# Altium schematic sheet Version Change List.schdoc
size 645 x 190 mm
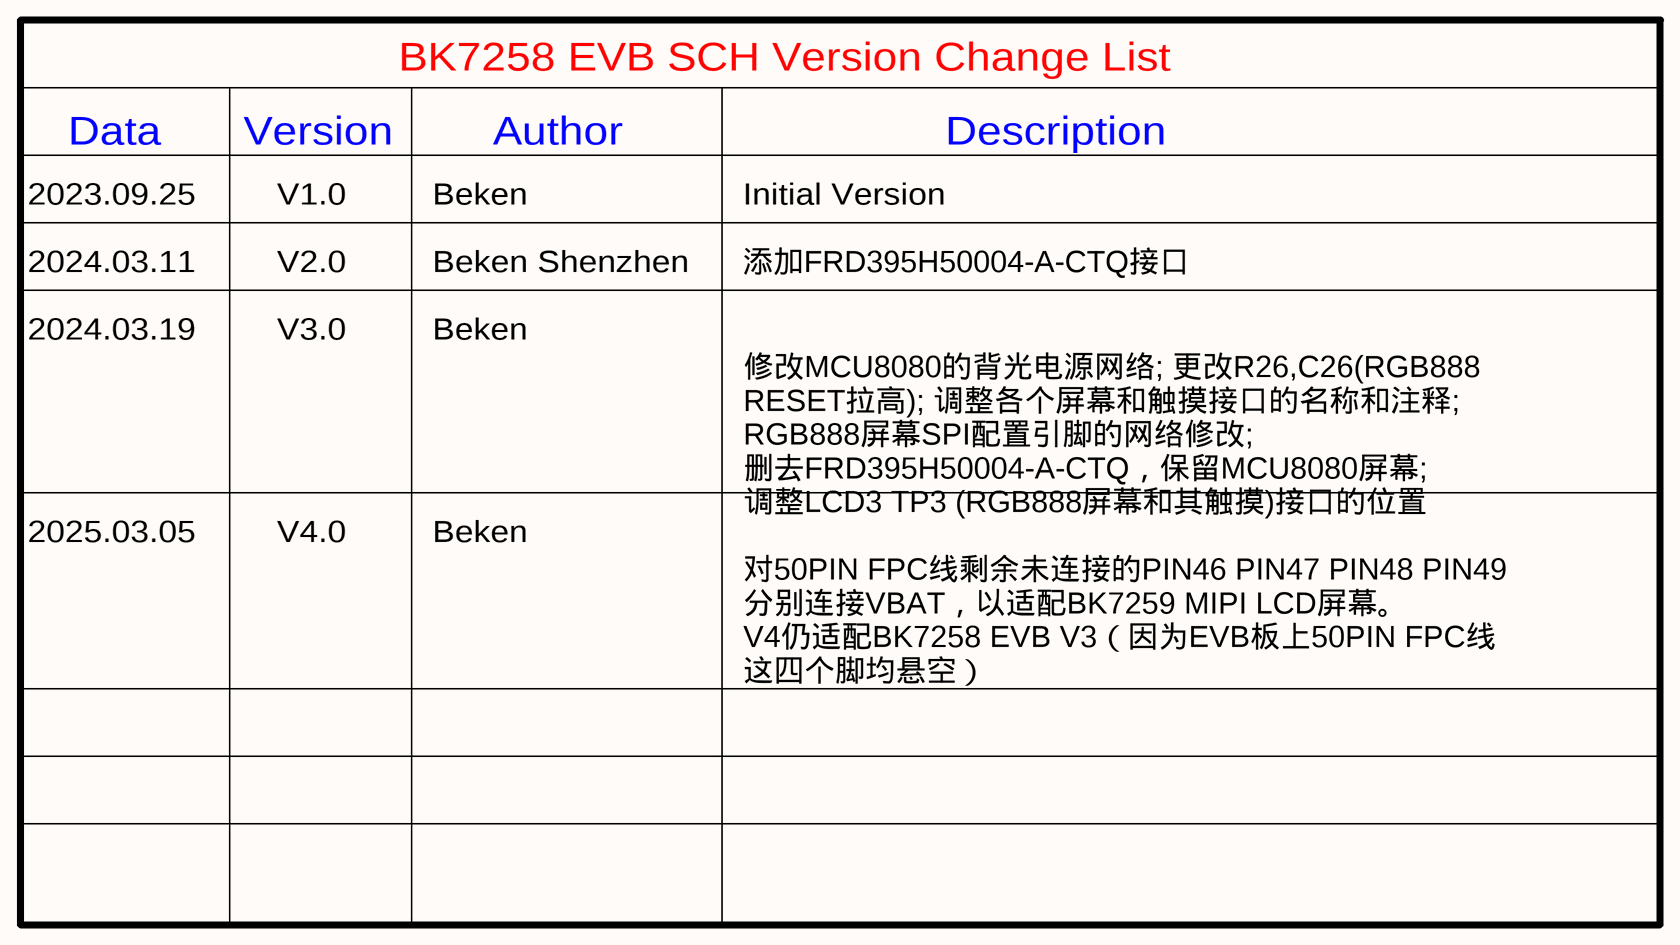
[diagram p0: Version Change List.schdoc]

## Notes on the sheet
- BK7258 EVB SCH Version Change List
- Data
- Version
- Author
- Description
- 2023.09.25
- V1.0
- Beken
- Initial Version
- 2024.03.11
- V2.0
- Beken Shenzhen
- 添加FRD395H50004-A-CTQ接口
- 2024.03.19
- V3.0
- 修改MCU8080的背光电源网络; 更改R26,C26(RGB888
  RESET拉高); 调整各个屏幕和触摸接口的名称和注释;
  RGB888屏幕SPI配置引脚的网络修改;
  删去FRD395H50004-A-CTQ，保留MCU8080屏幕;
  调整LCD3 TP3 (RGB888屏幕和其触摸)接口的位置
- 2025.03.05
- V4.0
- 对50PIN FPC线剩余未连接的PIN46 PIN47 PIN48 PIN49
  分别连接VBAT，以适配BK7259 MIPI LCD屏幕。
  V4仍适配BK7258 EVB V3（因为EVB板上50PIN FPC线
  这四个脚均悬空）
